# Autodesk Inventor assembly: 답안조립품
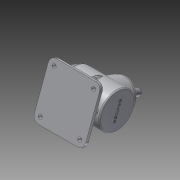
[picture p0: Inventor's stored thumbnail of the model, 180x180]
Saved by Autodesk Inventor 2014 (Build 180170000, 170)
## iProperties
Created: 2015-07
Part Number: 답안조립품
Document SubType Name: Assembly
Designer: user
Author: user
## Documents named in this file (14)
- C:\Users\user\Desktop\450706V1015\답안조립품.iam
- C:\Users\user\Desktop\450706V1015\본체.ipt
- C:\Users\user\Desktop\450706V1015\메인 축.ipt
- 메인 축.ipt
- C:\Users\user\Desktop\450706V1015\서브 축.ipt
- 서브 축.ipt
- C:\Users\user\Desktop\450706V1015\커버.ipt
- C:\Users\user\Desktop\450706V1015\베어링 6203.ipt
- C:\Users\user\Desktop\450706V1015\오일실.ipt
- C:\Users\user\Desktop\450706V1015\메인 베벨기어.ipt
- C:\Users\user\Desktop\450706V1015\키 5x5.ipt
- C:\Users\user\Desktop\450706V1015\서브 베벨기어.ipt
- C:\Users\user\Desktop\450706V1015\키 4x4.ipt
- C:\Users\user\Desktop\450706V1015\M4.ipt
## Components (8 placed, 1 different names)
1. M4:2 — Insert:13
2. M4:3
3. M4:4
4. M4:5
5. M4:1 — Insert:12
6. M4:6
7. M4:7
8. M4:8
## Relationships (2: Insert 2)
- Insert:12: M4:1
- Insert:13: M4:2
